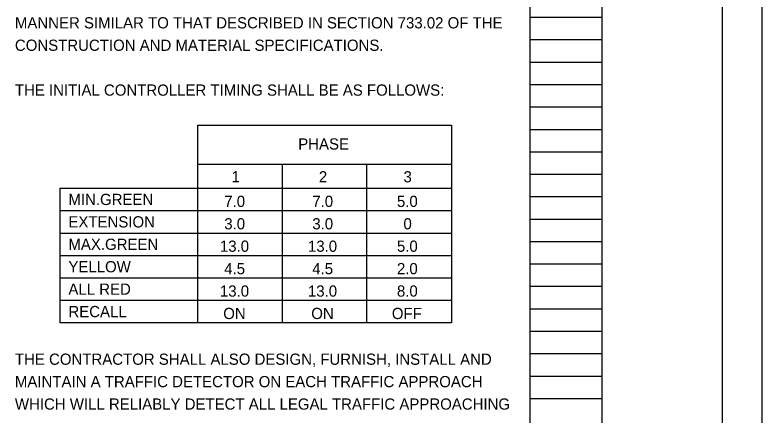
# Model space of a CAD drawing. Extents: x 0 to 34, y 0 to 33.4.
# Drawn here: x 24.66 to 34, y 5.25 to 10.25 of the extents above; entities that cross this region are included whole.
import ezdxf

# ---------------------------------------------------------------- set-up
doc = ezdxf.new("R2010")
doc.units = 0
for name, color, linetype in [('SH_Border', 7, 'Continuous'), ('SH_Cut_Line', 7, 'Continuous'), ('SH_Data', 7, 'Continuous'), ('TX_X_20', 7, 'Continuous')]:
    doc.layers.add(name, color=color, linetype=linetype)

msp = doc.modelspace()

# ---------------------------------------------------------------- linework, layer by layer
at = {"layer": 'SH_Border'}
msp.add_line((32, 0.5), (32, 21.5), dxfattribs=at)
msp.add_lwpolyline([(1.5, 21.5), (33.5, 21.5), (33.5, 0.5), (1.5, 0.5)], close=True, dxfattribs=at)
at = {"layer": 'SH_Cut_Line'}
msp.add_lwpolyline([(0, 0), (34, 0), (34, 22), (0, 22)], close=True, dxfattribs=at)
at = {"layer": 'SH_Data'}
for p, q in [((31.1, 0.98), (31.1, 21.14)), ((32, 0.98), (32, 21.14)), ((31.1, 10.22), (32, 10.22)), ((31.1, 9.94), (32, 9.94)), ((31.1, 9.66), (32, 9.66)), ((31.1, 9.38), (32, 9.38)), ((31.1, 9.1), (32, 9.1)), ((31.1, 8.82), (32, 8.82)), ((31.1, 8.54), (32, 8.54)), ((31.1, 8.26), (32, 8.26)), ((31.1, 7.98), (32, 7.98)), ((31.1, 7.7), (32, 7.7)), ((31.1, 7.42), (32, 7.42)), ((31.1, 7.14), (32, 7.14)), ((31.1, 6.86), (32, 6.86)), ((31.1, 6.58), (32, 6.58)), ((31.1, 6.3), (32, 6.3)), ((31.1, 6.02), (32, 6.02)), ((31.1, 5.74), (32, 5.74)), ((31.1, 5.46), (32, 5.46))]:
    msp.add_line(p, q, dxfattribs=at)
at = {"layer": 'TX_X_20'}
for p, q in [((26.9458, 8.085), (26.9458, 8.8701)), ((26.9458, 8.3869), (30.1181, 8.3869)), ((28.0032, 6.405), (28.0032, 8.3869)), ((29.0606, 6.405), (29.0606, 8.3869)), ((25.2255, 8.085), (30.1181, 8.085)), ((25.2255, 6.405), (25.2255, 8.085)), ((25.2255, 8.085), (26.9458, 8.085)), ((26.9458, 6.405), (26.9458, 8.085)), ((25.2255, 7.805), (30.1181, 7.805)), ((25.2255, 7.525), (30.1181, 7.525)), ((25.2255, 7.245), (30.1181, 7.245)), ((25.2255, 6.965), (30.1181, 6.965)), ((25.2255, 6.685), (30.1181, 6.685))]:
    msp.add_line(p, q, dxfattribs=at)
msp.add_lwpolyline([(26.9458, 8.8701), (30.1181, 8.8701), (30.1181, 6.405), (25.2255, 6.405)], dxfattribs=at)

# ---------------------------------------------------------------- texts
for s, p in [('MANNER SIMILAR TO THAT DESCRIBED IN SECTION 733.02 OF THE ', (24.66, 10.08)), ('CONSTRUCTION AND MATERIAL SPECIFICATIONS.', (24.66, 9.8)), ('THE INITIAL CONTROLLER TIMING SHALL BE AS FOLLOWS:', (24.66, 9.24)), ('PHASE', (28.2015, 8.5674)), ('1', (27.3673, 8.1577)), ('2', (28.4597, 8.1577)), ('3', (29.5179, 8.1577)), ('MIN.GREEN', (25.3288, 7.8747)), ('7.0', (27.2773, 7.851)), ('7.0', (28.3778, 7.851)), ('5.0', (29.4356, 7.851)), ('EXTENSION', (25.3288, 7.5947)), ('3.0', (27.2773, 7.571)), ('3.0', (28.3778, 7.571)), ('0', (29.5171, 7.571)), ('MAX.GREEN', (25.3288, 7.3147)), ('13.0', (27.223, 7.291)), ('13.0', (28.3235, 7.291)), ('5.0', (29.4356, 7.291)), ('YELLOW', (25.3288, 7.0347)), ('4.5', (27.2766, 7.011)), ('4.5', (28.3771, 7.011)), ('2.0', (29.4356, 7.011)), ('ALL RED', (25.3288, 6.7547)), ('13.0', (27.223, 6.731)), ('13.0', (28.3235, 6.731)), ('8.0', (29.4356, 6.731)), ('RECALL', (25.3288, 6.4747)), ('ON', (27.2644, 6.451)), ('ON', (28.3649, 6.451)), ('OFF', (29.372, 6.451)), ('THE CONTRACTOR SHALL ALSO DESIGN, FURNISH, INSTALL AND ', (24.66, 5.88)), ('MAINTAIN A TRAFFIC DETECTOR ON EACH TRAFFIC APPROACH ', (24.66, 5.6)), ('WHICH WILL RELIABLY DETECT ALL LEGAL TRAFFIC APPROACHING ', (24.66, 5.32))]:
    msp.add_text(s, height=0.14, dxfattribs=at).set_placement(p)

doc.saveas('drawing.dxf')
